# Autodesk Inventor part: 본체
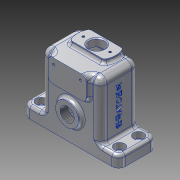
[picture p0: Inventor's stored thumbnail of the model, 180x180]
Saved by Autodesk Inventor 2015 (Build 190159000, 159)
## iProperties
Created: 2023-12
Part Number: 본체
Material: 알루미늄 6061
Document SubType Name: Modeling
Designer: user
Density: 2.7 g/cm^3
Appearance: 알루미늄 - 평지
Mass: 220.023 g
Surface Area: 358.826 cm^2
Volume: 81.4901 cm^3
Author: user
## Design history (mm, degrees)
sketch "스케치1"
  geometry: L1 (-50, -20)-(50, -20); L2 (50, -20)-(50, 20); L3 (50, 20)-(-50, 20); L4 (-50, 20)-(-50, -20); L5 (-50, -20)-(50, 20); L6 (50, -20)-(-50, 20); 1 further point
  constraints: 12 end point, 2 midpoint, 2 parallel, 1 horizontal, 1 perpendicular
  dimensions: "d0" = 100 distance of L2.end L3.end; "d1" = 40 distance of L1.end L2.end
extrude "돌출1" new body sketch "스케치1" distance "d2" = 12; taper "d3" = 0 deg
sketch "스케치2"
  geometry: L1 (-31, -20)-(31, -20); L2 (31, -20)-(31, 20); L3 (31, 20)-(-31, 20); L4 (-31, 20)-(-31, -20); L5 (-31, -20)-(31, 20); L6 (31, -20)-(-31, 20); 1 further point
  constraints: 12 end point, 2 midpoint, 2 parallel, 1 horizontal, 1 perpendicular
  dimensions: "d4" = 62 distance of L2.end L3.end; "d5" = 40 distance of L1.end L2.end
extrude "돌출2" join sketch "스케치2" distance "d6" = 60; taper "d7" = 0 deg
sketch "스케치3"
  geometry: L1 (19, 72)-(81, 72) reference; L2 (30, 72)-(70, 72); L3 (70, 72)-(70, 48); L4 (70, 48)-(30, 48); L5 (30, 48)-(30, 72); 3 further points
  constraints: 8 end point, 2 coincident, 2 midpoint, 2 parallel, 1 horizontal, 1 perpendicular
  dimensions: "d8" = 40 distance of L2.start L2.end; "d9" = 24 distance of L2.end L3.end
extrude "돌출3" join sketch "스케치3" distance "d10" = 4; taper "d11" = 0 deg
sketch "스케치4"
  geometry: L1 (50, -20)-(-50, -20) reference; L2 (27, 16)-(-27, 16); L3 (-27, 16)-(-27, -16); L4 (-27, -16)-(27, -16); L5 (27, -16)-(27, 16); L6 (27, 16)-(-27, -16); L7 (-27, 16)-(27, -16); 1 further point
  constraints: 12 end point, 2 midpoint, 2 parallel, 1 horizontal, 1 perpendicular
  dimensions: "d12" = 4 distance between parallel lines of L1 L4; "d13" = 54 distance of L3.end L4.end
extrude "돌출4" cut sketch "스케치4" distance "d14" = 68; taper "d15" = 0 deg
sketch "스케치5"
  geometry: L1 (0, 0)-(100, 0) reference; C1 r 12 at (50, 28); 2 further points
  constraints: 1 centre point, 1 midpoint, 1 vertical alignment
  dimensions: "d16" = 28 distance of C1.centre point (50, 0); "d17" = 24 diameter of C1
extrude "돌출5" join sketch "스케치5" distance "d18" = 4; taper "d19" = 0 deg
fillet "모깎기1" dims "d26" = 7
fillet "모깎기2" dims "d27" = 7
node "작업 평면1"
sketch "스케치7"
  geometry: L1 (20, -24)-(-20, -24) reference; L2 (-17.321, 17)-(17.321, 17); L3 (-17.321, -3)-(17.321, -3); A1 r 20 centre (0, 7) between (-17.321, 17) and (-17.321, -3); A2 r 20 centre (0, 7) between (17.321, -3) and (17.321, 17); 1 further point
  constraints: 4 end point, 4 point on circle, 2 centre point, 1 horizontal, 1 parallel, 1 vertical alignment
  dimensions: "d30" = 31 distance from line of A1.centre L1; "d31" = 10 distance from line of L2 A1.centre; "d32" = 20 distance between parallel lines of L3 L2; "d33" = 20 radius of A1; "d34" = 20 radius of A2
extrude "돌출6" join sketch "스케치7" stored distance "d35" = 4; taper "d36" = 0 deg
sketch "스케치8"
  geometry: C1 r 8 at (0, 7); A1 r 20 centre (0, 7) between (17.321, -3) and (17.321, 17) reference; 1 further point
  constraints: 1 centre point, 1 coincident
  dimensions: "d37" = 16 diameter of C1
extrude "돌출7" cut sketch "스케치8" distance "d38" = 100; taper "d39" = 0 deg
chamfer "모따기1" distance "d40" = 1; stored, may be unused: second distance "d41" = 2, angle "d42" = 45 deg
sketch "스케치9"
  geometry: A1 r 20 centre (0, 7) between (-17.321, 17) and (-17.321, -3) reference; 2 further points
  constraints: 1 horizontal alignment
  dimensions: "d43" = 14 distance of point (-14, 7) A1.centre
hole "구멍1" sketch "스케치9" at (-14, 7) diameter "d44" = 2.459; stored, may be unused: countersink angle "d48" = 90 deg, drill point angle "d50" = 118 deg; dims "d45" = 6, "d46" = 4, "d47" = 2, "d49" = 8
fillet "모깎기3" dims "d51" = 7
sketch "스케치10"
  geometry: C1 r 12 at (24, 37) reference; C2 r 20 at (24, 37); 1 further point
  constraints: 1 centre point, 1 coincident
  dimensions: "d88" = 40 diameter of C2
extrude "돌출8" join sketch "스케치10" distance "d89" = 4; taper "d90" = 0 deg
hole "구멍6" diameter "d93" = 18; stored, may be unused: countersink angle "d97" = 90 deg, drill point angle "d99" = 118 deg; dims "d91" = 10, "d92" = 10, "d94" = 6, "d95" = 11, "d96" = 6.6, "d98" = 30
chamfer "모따기2" distance "d100" = 1; stored, may be unused: second distance "d101" = 2, angle "d102" = 45 deg
hole "구멍7" diameter "d105" = 14.917; stored, may be unused: countersink angle "d109" = 90 deg, drill point angle "d111" = 118 deg; dims "d106" = 32, "d107" = 11, "d108" = 6.6, "d110" = 25, "d158" = 10, "d159" = 10
sketch "스케치11"
  geometry: L1 (0, 0)-(0, -15); C1 r 10 at (0, 0) reference; 1 further point
  constraints: 2 end point, 1 vertical
  dimensions: "d112" = 15 distance of L1.start L1.end
hole "구멍8" sketch "스케치11" at (0, -15) diameter "d113" = 2.459; stored, may be unused: countersink angle "d117" = 90 deg, drill point angle "d119" = 118 deg; dims "d114" = 6, "d115" = 11, "d116" = 6.6, "d118" = 15
fillet "모깎기4" dims "d123" = 3
fillet "모깎기5" dims "d124" = 3
fillet "모깎기6" dims "d125" = 3
fillet "모깎기7" dims "d126" = 3
fillet "모깎기8" dims "d127" = 3
fillet "모깎기9" dims "d128" = 3
fillet "모깎기10" dims "d129" = 3
fillet "모깎기11" dims "d130" = 3
sketch "스케치12"
  geometry: 2 further points
  dimensions: "d131" = 10 vertical distance of point (-41, 10) point (0, 0); "d132" = 41 horizontal distance of point (-41, 10) point (0, 0)
hole "구멍9" sketch "스케치12" at (-41, 10) diameter "d133" = 6.6; stored, may be unused: countersink angle "d137" = 90 deg, drill point angle "d139" = 118 deg; dims "d134" = 6, "d135" = 11, "d136" = 6.6, "d138" = 15
fillet "모깎기12" dims "d140" = 3
fillet "모깎기13" dims "d141" = 3
fillet "모깎기14" dims "d142" = 5
fillet "모깎기15" dims "d143" = 3
fillet "모깎기16" dims "d144" = 5
sketch "스케치13"
  geometry: L1 (25, -11)-(49, -11) reference; L2 (65, 0)-(65, 26) reference; 2 further points
  constraints: 1 other
  dimensions: "d145" = 23 distance from line of point (25, 12) L1; "d146" = 40 distance from line of point (25, 12) L2
feature "엠보싱1" sketch "스케치13" dims "d147" = 0.5, "d148" = 0
sketch "스케치14"
  geometry: L1 (65, 72)-(35, 72) reference; 2 further points
  dimensions: "d149" = 6 distance from line of point (36, 66) L1; "d150" = 14 horizontal distance of point (36, 66) point (50, 0)
hole "구멍10" sketch "스케치14" at (36, 66) diameter "d151" = 2.459; stored, may be unused: countersink angle "d155" = 90 deg, drill point angle "d157" = 118 deg; dims "d152" = 6, "d153" = 11, "d154" = 6.6, "d156" = 15
node "솔리드1"
mirror "대칭1"
pattern_circular "원형 패턴1" dims angle "d121" = 360 deg
mirror "대칭2"
mirror "대칭3"
mirror "대칭4"
other parameters: "d28" = 4
